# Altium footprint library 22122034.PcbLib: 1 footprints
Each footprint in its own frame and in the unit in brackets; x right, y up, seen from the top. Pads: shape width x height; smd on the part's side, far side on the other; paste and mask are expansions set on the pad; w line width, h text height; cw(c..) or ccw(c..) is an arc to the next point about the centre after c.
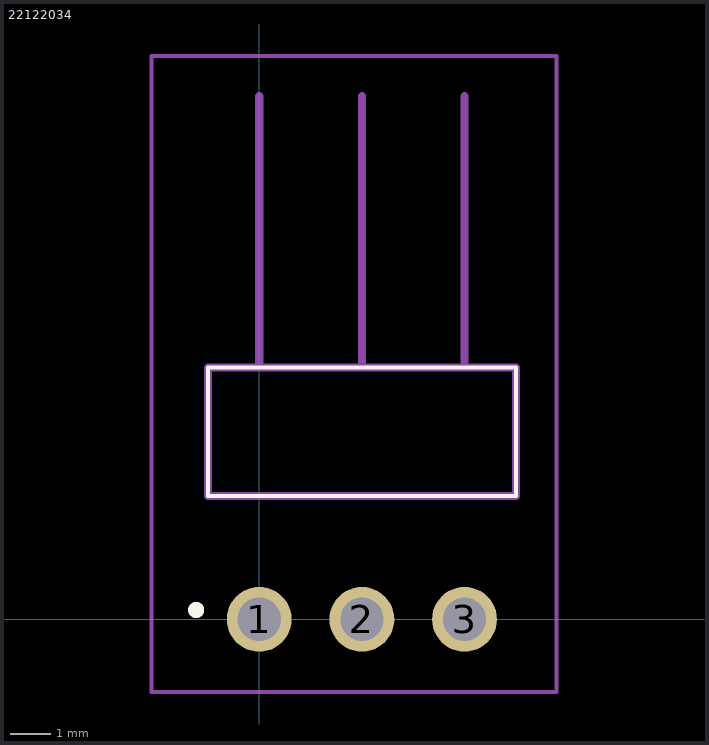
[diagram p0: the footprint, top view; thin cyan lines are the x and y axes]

## 22122034 [mm]
pads (3):
  round 1.605 hole 1.07: 1(0,0) 2(2.54,0) 3(5.08,0)
Top Overlay:
  lines w0.1: -1.27,3.05 6.35,3.05 6.35,6.23 -1.27,6.23 -1.27,3.05
  lines w0.2: -1.66,0.23 cw(c-1.56,0.23) -1.46,0.23 ; -1.66,0.23 -1.66,0.23 ; -1.66,0.23 ccw(c-1.56,0.23) -1.46,0.23 ; -1.46,0.23 -1.46,0.23
Mechanical 15:
  lines w0.2: 0,6.23 0,12.94 ; 2.54,6.23 2.54,12.94 ; 5.08,6.23 5.08,12.94 ; -1.27,3.05 6.35,3.05 6.35,6.23 -1.27,6.23 -1.27,3.05
Mechanical 20:
  lines w0.1: -2.66,-1.803 7.35,-1.803 7.35,13.94 -2.66,13.94 -2.66,-1.803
